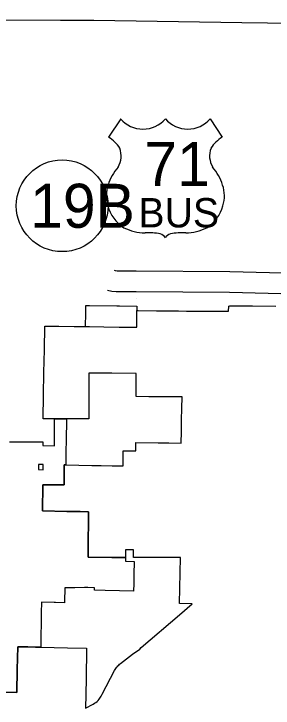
# Model space of a CAD drawing. Extents: x 670147 to 673275, y 705573 to 707613.
# Drawn here: x 670396 to 670451.9, y 707269.4 to 707419.3 of the extents above; entities that cross this region are included whole.
import ezdxf

# ---------------------------------------------------------------- set-up
doc = ezdxf.new("R2010")
doc.units = 0
for name, color, linetype in [('10', 7, 'Continuous'), ('15', 7, 'Continuous'), ('16', 7, 'Continuous'), ('22', 7, 'Continuous'), ('27', 7, 'Continuous'), ('6', 7, 'Continuous')]:
    doc.layers.add(name, color=color, linetype=linetype)

msp = doc.modelspace()

# ---------------------------------------------------------------- linework, layer by layer
at = {"layer": '10'}
for points in [[(670406.07, 707417.87), (670387.93, 707417.95), (670348.42, 707418.84), (670325.75, 707419.28)], [(670445.2, 707417.37), (670413.23, 707417.84), (670411.7, 707417.85), (670406.07, 707417.87)], [(670481.09, 707416.85), (670472.89, 707417.02), (670445.2, 707417.37)]]:
    msp.add_lwpolyline(points, dxfattribs=at)
at = {"layer": '15'}
for points in [[(670471.1, 707362.85), (670442.63, 707363.61), (670422.36, 707363.76), (670418.26, 707363.75), (670417.93, 707363.77), (670417.68, 707363.84)], [(670470.31, 707358.37), (670442.56, 707359.11), (670422.35, 707359.26), (670418.06, 707359.24), (670417.14, 707359.33), (670416.18, 707359.59)]]:
    msp.add_lwpolyline(points, dxfattribs=at)
at = {"layer": '16'}
msp.add_line((670422.42, 707357.88), (670422.43, 707357.88), dxfattribs=at)
at = {"layer": '22'}
for p, q in [((670419.04, 707396.65), (670416.44, 707392.64)), ((670438.34, 707396.65), (670440.94, 707392.64))]:
    msp.add_line(p, q, dxfattribs=at)
for centre, radius, start, end in [((670423.87, 707400.72), 6.32, 220.075, 319.6701), ((670433.51, 707400.72), 6.32, 220.3299, 319.925), ((670413.05, 707386.81), 6.75, 30.7809, 59.9883), ((670444.33, 707386.81), 6.75, 120.0117, 149.2191), ((670414.53, 707388.59), 4.62, 328.8105, 21.2108), ((670442.85, 707388.59), 4.62, 158.7892, 211.1895), ((670426.62, 707379.11), 10.79, 138.9565, 162.6913), ((670430.75, 707379.11), 10.79, 17.3087, 41.0435), ((670423.06, 707380), 7.13, 160.9576, 197.3819), ((670434.31, 707380), 7.13, 342.6181, 19.0424), ((670424.22, 707380.02), 8.25, 195.1074, 237.1312), ((670433.15, 707380.02), 8.25, 302.8688, 344.8926), ((670424.38, 707382.61), 10.59, 244.0771, 269.5779), ((670433, 707382.61), 10.59, 270.4221, 295.9229), ((670424.62, 707352.63), 19.4, 81.1942, 90.9539), ((670427.05, 707370.02), 1.86, 28.0342, 72.9864), ((670430.33, 707370.02), 1.86, 107.0136, 151.9658), ((670432.76, 707352.63), 19.4, 89.0461, 98.8058)]:
    msp.add_arc(centre, radius, start, end, dxfattribs=at)
at = {"layer": '27'}
msp.add_circle((670406.41, 707377.85), 9.9, dxfattribs=at)
at = {"layer": '6'}
for points in [[(670395.02, 707326.91), (670397.3, 707326.88), (670399.83, 707326.91), (670402.26, 707326.86), (670402.25, 707326.18), (670402.25, 707326.08), (670404.76, 707326.05), (670404.78, 707327.05), (670404.79, 707331.85), (670402.31, 707331.85), (670402.38, 707336.93), (670402.45, 707341.86), (670402.63, 707346.73), (670402.67, 707351.86), (670402.67, 707351.87), (670405.72, 707351.83), (670408.99, 707351.79), (670411.46, 707351.76), (670411.49, 707354.63), (670411.49, 707356.28), (670411.49, 707356.31), (670411.49, 707356.35), (670412.34, 707356.34), (670418.2, 707356.27), (670418.77, 707356.26), (670422.55, 707356.2), (670422.54, 707355.21), (670422.81, 707355.21), (670426.74, 707355.18), (670431.45, 707355.14), (670431.54, 707355.14), (670433.28, 707355.13), (670434.97, 707355.12), (670435.21, 707355.12), (670437.61, 707355.1), (670442.35, 707355.06), (670442.36, 707356.16), (670442.59, 707356.27), (670442.61, 707356.26), (670442.81, 707356.26), (670442.85, 707356.26), (670444.32, 707356.25), (670445.1, 707356.24), (670447.03, 707356.22), (670447.5, 707356.21), (670452.51, 707356.16)], [(670421.82, 707303.58), (670420.05, 707303.59), (670420.09, 707301.93), (670418.8, 707301.94), (670417.1, 707301.94), (670412.05, 707301.96), (670412.05, 707304.48), (670412.05, 707304.77), (670412.05, 707306.96), (670412.06, 707308.12), (670412.06, 707309.26), (670412.06, 707309.42), (670412.07, 707311.8), (670410.3, 707311.82), (670407.39, 707311.87), (670402.18, 707311.95), (670402.27, 707317.6), (670406.84, 707317.57), (670406.85, 707321.89), (670407.21, 707321.88), (670412.85, 707321.79), (670414.8, 707321.76), (670414.85, 707321.76), (670417.22, 707321.72), (670419.55, 707321.68), (670419.58, 707324.95), (670420.54, 707324.94), (670422.29, 707324.93), (670422.3, 707326.77), (670427.11, 707326.69), (670429.41, 707326.65), (670432.1, 707326.6), (670432.15, 707329.13), (670432.2, 707331.62), (670432.25, 707334.09), (670432.29, 707336.57), (670427.28, 707336.62), (670425.12, 707336.63), (670422.37, 707336.66), (670422.41, 707341.62), (670417.15, 707341.68), (670412.19, 707341.74), (670412.18, 707338.51), (670412.16, 707336.8), (670412.15, 707331.85), (670407.31, 707331.85), (670404.79, 707331.85), (670402.31, 707331.85), (670402.38, 707336.93), (670402.45, 707341.86), (670402.63, 707346.73), (670402.67, 707351.86), (670402.67, 707351.87), (670405.72, 707351.83), (670408.99, 707351.79), (670411.46, 707351.76), (670412.31, 707351.76), (670415.41, 707351.71), (670418.75, 707351.67), (670421.01, 707351.65), (670422.5, 707351.63), (670422.53, 707354.05), (670422.54, 707355.21), (670422.81, 707355.21), (670426.74, 707355.18), (670431.45, 707355.14), (670431.54, 707355.14), (670433.28, 707355.13), (670434.97, 707355.12), (670435.21, 707355.12), (670437.61, 707355.1), (670442.35, 707355.06), (670442.36, 707356.16), (670442.59, 707356.27), (670442.61, 707356.26), (670442.81, 707356.26), (670442.85, 707356.26), (670444.32, 707356.25), (670445.1, 707356.24), (670447.03, 707356.22), (670447.5, 707356.21), (670452.51, 707356.16)], [(670395.02, 707326.91), (670397.3, 707326.88), (670399.83, 707326.91), (670402.26, 707326.86), (670402.25, 707326.18), (670402.25, 707326.08), (670404.76, 707326.05), (670404.78, 707327.05), (670404.79, 707331.85), (670407.31, 707331.85), (670407.25, 707327.01), (670407.22, 707325.03), (670407.21, 707321.88), (670406.85, 707321.89), (670406.84, 707317.57), (670402.27, 707317.6), (670402.18, 707311.95), (670407.39, 707311.87), (670410.3, 707311.82), (670412.07, 707311.8), (670412.06, 707309.42), (670412.06, 707309.26), (670412.06, 707308.12), (670412.05, 707306.96), (670412.05, 707304.77), (670412.05, 707304.48), (670412.05, 707301.96), (670417.1, 707301.94), (670418.8, 707301.94), (670420.09, 707301.93), (670420.1, 707301.93), (670420.08, 707301.08), (670421.94, 707301.04), (670421.89, 707298.26), (670421.85, 707296.26), (670421.82, 707294.67), (670418.78, 707294.74), (670415.7, 707294.8), (670413.37, 707294.86), (670413.39, 707295.38), (670411.93, 707295.41), (670411.21, 707295.4), (670409.11, 707295.38), (670407.01, 707295.36)], [(670391.68, 707272.84), (670396.63, 707272.73), (670396.73, 707277.69), (670396.82, 707282.62), (670397, 707282.62), (670398.99, 707282.59), (670400.65, 707282.56), (670401.77, 707282.55), (670407.59, 707282.43), (670411.68, 707282.35), (670411.56, 707275.61), (670411.5, 707272.57), (670411.5, 707272.43), (670411.5, 707272.29), (670411.44, 707269.38), (670413.1, 707270.25), (670413.4, 707270.42), (670413.69, 707270.62), (670413.94, 707270.83), (670414.15, 707271.04), (670414.38, 707271.29), (670414.56, 707271.54), (670414.71, 707271.77), (670414.84, 707271.99), (670415.03, 707272.36), (670415.06, 707272.36), (670417.72, 707277.49), (670417.86, 707277.75), (670417.98, 707277.94), (670418.13, 707278.14), (670418.26, 707278.31), (670418.42, 707278.5), (670418.61, 707278.69), (670418.8, 707278.86), (670418.97, 707278.99), (670421.57, 707281), (670423.16, 707282.14), (670423.45, 707282.47), (670431.71, 707289.54), (670434.5, 707291.92), (670431.75, 707291.96), (670431.92, 707301.9), (670421.96, 707301.93), (670421.79, 707301.93), (670421.82, 707303.58)], [(670407.01, 707295.36), (670406.94, 707292.37), (670406.93, 707292.11), (670404.96, 707292.17), (670404.7, 707292.17), (670401.95, 707292.23), (670401.91, 707289.98), (670401.86, 707287.63), (670401.86, 707287.53), (670401.86, 707287.2), (670401.83, 707285.5), (670401.8, 707284.05), (670401.77, 707282.55), (670400.65, 707282.56), (670398.99, 707282.59), (670397, 707282.62), (670396.82, 707282.62), (670396.73, 707277.69), (670396.63, 707272.73), (670391.68, 707272.84)]]:
    msp.add_lwpolyline(points, dxfattribs=at)
msp.add_lwpolyline([(670402.31, 707320.87), (670402.3, 707321.97), (670402.21, 707321.97), (670401.27, 707321.98), (670401.28, 707321.26), (670401.28, 707321.22), (670401.29, 707320.93)], close=True, dxfattribs=at)

# ---------------------------------------------------------------- texts
at = {"layer": '22'}
for s, height, p in [('71', 9.504, (670424.15, 707382.12)), ('BUS', 6.336, (670422.86, 707373.18))]:
    msp.add_text(s, height=height, dxfattribs=at).set_placement(p)
at = {"layer": '27'}
msp.add_text('19B', height=9.504, dxfattribs=at).set_placement((670399.5, 707373.1))

doc.saveas('drawing.dxf')
